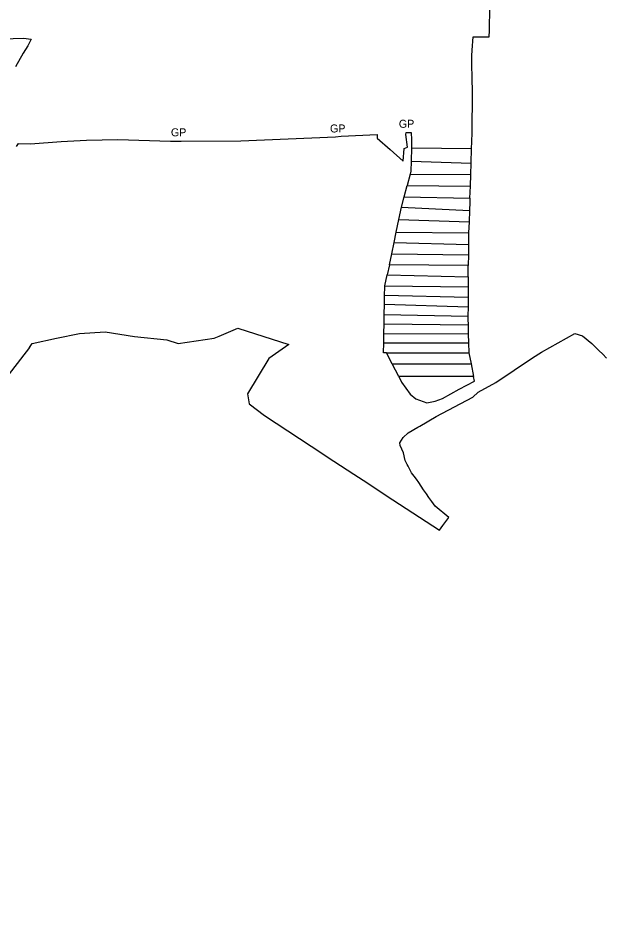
# Model space of a CAD drawing. Extents: x -534397 to -527742, y -1181460 to -1175250.
# Drawn here: x -530722 to -530094, y -1179657 to -1178694 of the extents above; entities that cross this region are included whole.
import ezdxf

# ---------------------------------------------------------------- set-up
doc = ezdxf.new("R2010")
doc.units = 0
doc.layers.add('Hranice obcí', color=7, linetype='Continuous')
doc.layers.add('Hranice parcel', color=7, linetype='Continuous')

msp = doc.modelspace()

# ---------------------------------------------------------------- linework, layer by layer
at = {"layer": 'Hranice obcí'}
for p, q in [((-530299.41, -1178833.62), (-530299.73, -1178847.89)), ((-530235.23, -1178850.15), (-530234.7, -1178834.3)), ((-530299.73, -1178847.89), (-530299.97, -1178858.59)), ((-530299.73, -1178847.89), (-530235.23, -1178850.15)), ((-530299.97, -1178858.59), (-530300.78, -1178861.66)), ((-530235.64, -1178862.34), (-530235.23, -1178850.15)), ((-530300.78, -1178861.66), (-530303.76, -1178873.82)), ((-530300.78, -1178861.66), (-530235.64, -1178862.34)), ((-530236.05, -1178874.65), (-530235.64, -1178862.34)), ((-530307.21, -1178885.97), (-530303.76, -1178873.82)), ((-530303.76, -1178873.82), (-530236.05, -1178874.65)), ((-530236.49, -1178887.44), (-530236.05, -1178874.65)), ((-530310.06, -1178897.34), (-530307.21, -1178885.97)), ((-530307.21, -1178885.97), (-530236.49, -1178887.44)), ((-530236.49, -1178887.44), (-530236.63, -1178891.74)), ((-530312.96, -1178910.48), (-530310.06, -1178897.34)), ((-530310.06, -1178897.34), (-530236.99, -1178900.75)), ((-530236.63, -1178891.74), (-530236.99, -1178900.75)), ((-530236.99, -1178900.75), (-530237.47, -1178913.05)), ((-530315.69, -1178923.9), (-530312.96, -1178910.48)), ((-530312.96, -1178910.48), (-530237.47, -1178913.05)), ((-530237.47, -1178913.05), (-530237.93, -1178924.65)), ((-530317.99, -1178935.23), (-530315.69, -1178923.9)), ((-530315.69, -1178923.9), (-530237.93, -1178924.65)), ((-530237.93, -1178924.65), (-530238.2, -1178931.44)), ((-530320.47, -1178947.37), (-530317.99, -1178935.23)), ((-530317.99, -1178935.23), (-530238.21, -1178937.4)), ((-530238.2, -1178931.44), (-530238.21, -1178937.4)), ((-530238.21, -1178937.4), (-530238.23, -1178948.37)), ((-530322.93, -1178958.98), (-530320.47, -1178947.37)), ((-530320.47, -1178947.37), (-530238.23, -1178948.37)), ((-530238.23, -1178948.37), (-530238.26, -1178959.85)), ((-530322.93, -1178958.98), (-530325.26, -1178969.95)), ((-530238.26, -1178959.85), (-530322.93, -1178958.98)), ((-530238.28, -1178970.94), (-530238.26, -1178959.85)), ((-530327.74, -1178981.67), (-530325.26, -1178969.95)), ((-530325.26, -1178969.95), (-530238.29, -1178971.88)), ((-530238.29, -1178971.88), (-530238.38, -1178982.76)), ((-530238.29, -1178971.88), (-530238.28, -1178970.94)), ((-530328.19, -1178991.57), (-530328.04, -1178983.1)), ((-530328.04, -1178983.1), (-530327.74, -1178981.67)), ((-530327.74, -1178981.67), (-530238.38, -1178982.76)), ((-530238.38, -1178982.76), (-530238.47, -1178993.69)), ((-530328.37, -1179001.28), (-530328.19, -1178991.57)), ((-530328.19, -1178991.57), (-530238.47, -1178993.69)), ((-530238.47, -1178993.69), (-530238.56, -1179004.18)), ((-530328.56, -1179012.29), (-530328.37, -1179001.28)), ((-530328.37, -1179001.28), (-530238.56, -1179004.18)), ((-530328.71, -1179022.61), (-530328.56, -1179012.29)), ((-530328.56, -1179012.29), (-530238.64, -1179014.13)), ((-530238.56, -1179004.18), (-530238.64, -1179014.13)), ((-530328.93, -1179032.94), (-530328.71, -1179022.61)), ((-530328.71, -1179022.61), (-530238.52, -1179023.7)), ((-530238.64, -1179014.13), (-530238.67, -1179017.56)), ((-530238.67, -1179017.56), (-530238.52, -1179023.7)), ((-530238.52, -1179023.7), (-530238.3, -1179033.3)), ((-530329.11, -1179042.9), (-530328.93, -1179032.94)), ((-530328.93, -1179032.94), (-530238.3, -1179033.3)), ((-530238.3, -1179033.3), (-530238.07, -1179042.83)), ((-530329.3, -1179053.72), (-530329.11, -1179042.9)), ((-530329.11, -1179042.9), (-530238.07, -1179042.83)), ((-530238.07, -1179042.83), (-530237.81, -1179053.68)), ((-530325.95, -1179053.72), (-530329.3, -1179053.72)), ((-530325.95, -1179053.72), (-530237.81, -1179053.68)), ((-530319.94, -1179065.38), (-530325.95, -1179053.72)), ((-530237.81, -1179053.68), (-530235.39, -1179065.35)), ((-530319.94, -1179065.38), (-530235.39, -1179065.35)), ((-530312.93, -1179078.97), (-530319.94, -1179065.38)), ((-530235.39, -1179065.35), (-530232.55, -1179079.04)), ((-530312.93, -1179078.97), (-530309.84, -1179084.96)), ((-530232.55, -1179079.04), (-530312.93, -1179078.97)), ((-530231.5, -1179084.07), (-530232.55, -1179079.04)), ((-530309.84, -1179084.96), (-530300.55, -1179097.83)), ((-530248.23, -1179092.49), (-530231.5, -1179084.07)), ((-530300.55, -1179097.83), (-530294.64, -1179103.02)), ((-530266.06, -1179102.77), (-530248.23, -1179092.49)), ((-530294.64, -1179103.02), (-530282.88, -1179107.41)), ((-530282.88, -1179107.41), (-530273.77, -1179105.53)), ((-530273.77, -1179105.53), (-530266.06, -1179102.77))]:
    msp.add_line(p, q, dxfattribs=at)
at = {"layer": 'Hranice parcel'}
for points in [[(-530308.18, -1178847.79), (-530307.26, -1178834.12), (-530303.48, -1178832.77), (-530305.22, -1178819.31), (-530305.07, -1178816.92), (-530299.66, -1178816.94), (-530299.22, -1178825.06), (-530299.41, -1178833.62), (-530234.7, -1178834.3), (-530234.45, -1178826.96), (-530234.27, -1178817.2), (-530234, -1178802.99), (-530233.72, -1178788.48), (-530233.63, -1178783.67), (-530233.83, -1178773.56), (-530234.13, -1178758.9), (-530234.43, -1178743.93), (-530234.53, -1178738.93), (-530234.61, -1178734.75), (-530234.17, -1178728.62), (-530233.15, -1178714.43), (-530215.79, -1178714.47), (-530215.5, -1178707.65), (-530214.77, -1178657.23)], [(-530760.05, -1178717.22), (-530715.94, -1178715.94), (-530707.41, -1178716.85), (-530711.31, -1178724.17), (-530716.16, -1178732.1), (-530724.24, -1178746.47)], [(-530723.13, -1178832.09), (-530721.15, -1178828.82), (-530708.43, -1178829.25), (-530675.52, -1178826.65), (-530675.52, -1178826.65), (-530648.32, -1178825.44), (-530614.53, -1178824.55), (-530558.11, -1178826.33), (-530546.7, -1178826.31), (-530482.56, -1178825.91), (-530380.76, -1178821.76), (-530374.66, -1178821.05), (-530335.95, -1178819.42), (-530336.07, -1178823.11), (-530322.24, -1178835.34), (-530308.18, -1178847.79)], [(-530709.4, -1179047.84), (-530706.61, -1179043.62), (-530680.52, -1179037.7), (-530655.72, -1179032.82), (-530627.98, -1179031.1), (-530596.62, -1179036.06), (-530561.99, -1179039.64), (-530549.61, -1179043.71), (-530511.14, -1179037.86), (-530505.9, -1179035.66)], [(-530505.9, -1179035.66), (-530485.87, -1179027.03), (-530430.81, -1179044.55), (-530452.3, -1179059.63), (-530475.25, -1179097.74), (-530473.63, -1179108.2), (-530457.2, -1179120.78), (-530406.88, -1179153.81), (-530382.62, -1179169.73), (-530361.34, -1179183.7), (-530346.29, -1179193.58), (-530326.53, -1179206.55), (-530269.38, -1179244.06), (-530265.8, -1179239.07), (-530259.32, -1179230.45)], [(-530259.32, -1179230.45), (-530274.02, -1179218.01), (-530277.49, -1179213.17), (-530280.6, -1179208.83), (-530283.31, -1179205.06), (-530286.5, -1179200.59), (-530291.28, -1179192.77), (-530294.02, -1179189.23), (-530296.57, -1179185.93), (-530299.27, -1179182.46), (-530301.14, -1179178.69), (-530302.94, -1179175.05), (-530303.78, -1179173.36), (-530305.99, -1179168.98), (-530307.78, -1179160.87), (-530311.26, -1179153.09), (-530311.63, -1179150.17), (-530308.18, -1179144.54), (-530302.7, -1179139.29), (-530292.54, -1179133.5), (-530290.34, -1179132.19), (-530272.81, -1179121.94), (-530233.35, -1179101.11), (-530227.76, -1179095.91), (-530208.58, -1179085.27), (-530169.38, -1179058.83), (-530159.73, -1179052.99), (-530123.83, -1179032.72), (-530115.56, -1179035.34), (-530105.63, -1179043.45), (-530097.99, -1179051.05), (-530093.98, -1179055.04), (-530090.03, -1179059.33)], [(-530709.4, -1179047.84), (-530770.06, -1179126.34), (-530798.46, -1179178.37), (-530832.59, -1179240.49), (-530886.78, -1179362.52), (-530947.03, -1179507.4), (-531010.42, -1179657.02)]]:
    msp.add_lwpolyline(points, dxfattribs=at)

# ---------------------------------------------------------------- texts
for p in [(-530386.77, -1178817.05), (-530312.86, -1178812.03), (-530557.54, -1178821.2)]:
    msp.add_text('GP', height=8.59, dxfattribs=at).set_placement(p)

doc.saveas('drawing.dxf')
